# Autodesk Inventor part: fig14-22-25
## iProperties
Created: 2005-03
Part Number: fig14-22-25
Document SubType Name: Sheet Metal
Designer: CADCIM
Manufacturer: Standard
Standards Organization: Custom
Author: CADCIM
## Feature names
1. Plate1
